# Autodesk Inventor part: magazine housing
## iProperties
Created: 2006-04
Part Number: magazine housing
Document SubType Name: Modeling
Designer: Калинин
Author: Калинин
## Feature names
1. Выдавливание1 [Extrusion]
2. Выдавливание2 [Extrusion]
3. Выдавливание3 [Extrusion]
4. Выдавливание4 [Extrusion]
5. Выдавливание5 [Extrusion]
6. Выдавливание6 [Extrusion]
7. Сопряжение1 [Fillet]
8. Выдавливание7 [Extrusion]
9. Выдавливание8 [Extrusion]
10. Выдавливание9 [Extrusion]
11. Выдавливание10 [Extrusion]
12. Выдавливание11 [Extrusion]
13. Сопряжение2 [Fillet]
14. Выдавливание12 [Extrusion]
15. Сопряжение3 [Fillet]
16. Сопряжение4 [Fillet]
17. Фаска1 [Chamfer]
18. Сопряжение5 [Fillet]
19. Фаска2 [Chamfer]
20. Сопряжение6 [Fillet]
21. Сопряжение7 [Fillet]
22. Сопряжение8 [Fillet]
23. Фаска3 [Chamfer]
24. Сопряжение9 [Fillet]
25. Сопряжение10 [Fillet]
26. Сопряжение11 [Fillet]
27. Сопряжение12 [Fillet]
28. Сопряжение13 [Fillet]
29. Сопряжение14 [Fillet]
30. Фаска4 [Chamfer]
31. Выдавливание13 [Extrusion]
32. Сопряжение15 [Fillet]
33. Сопряжение16 [Fillet]
